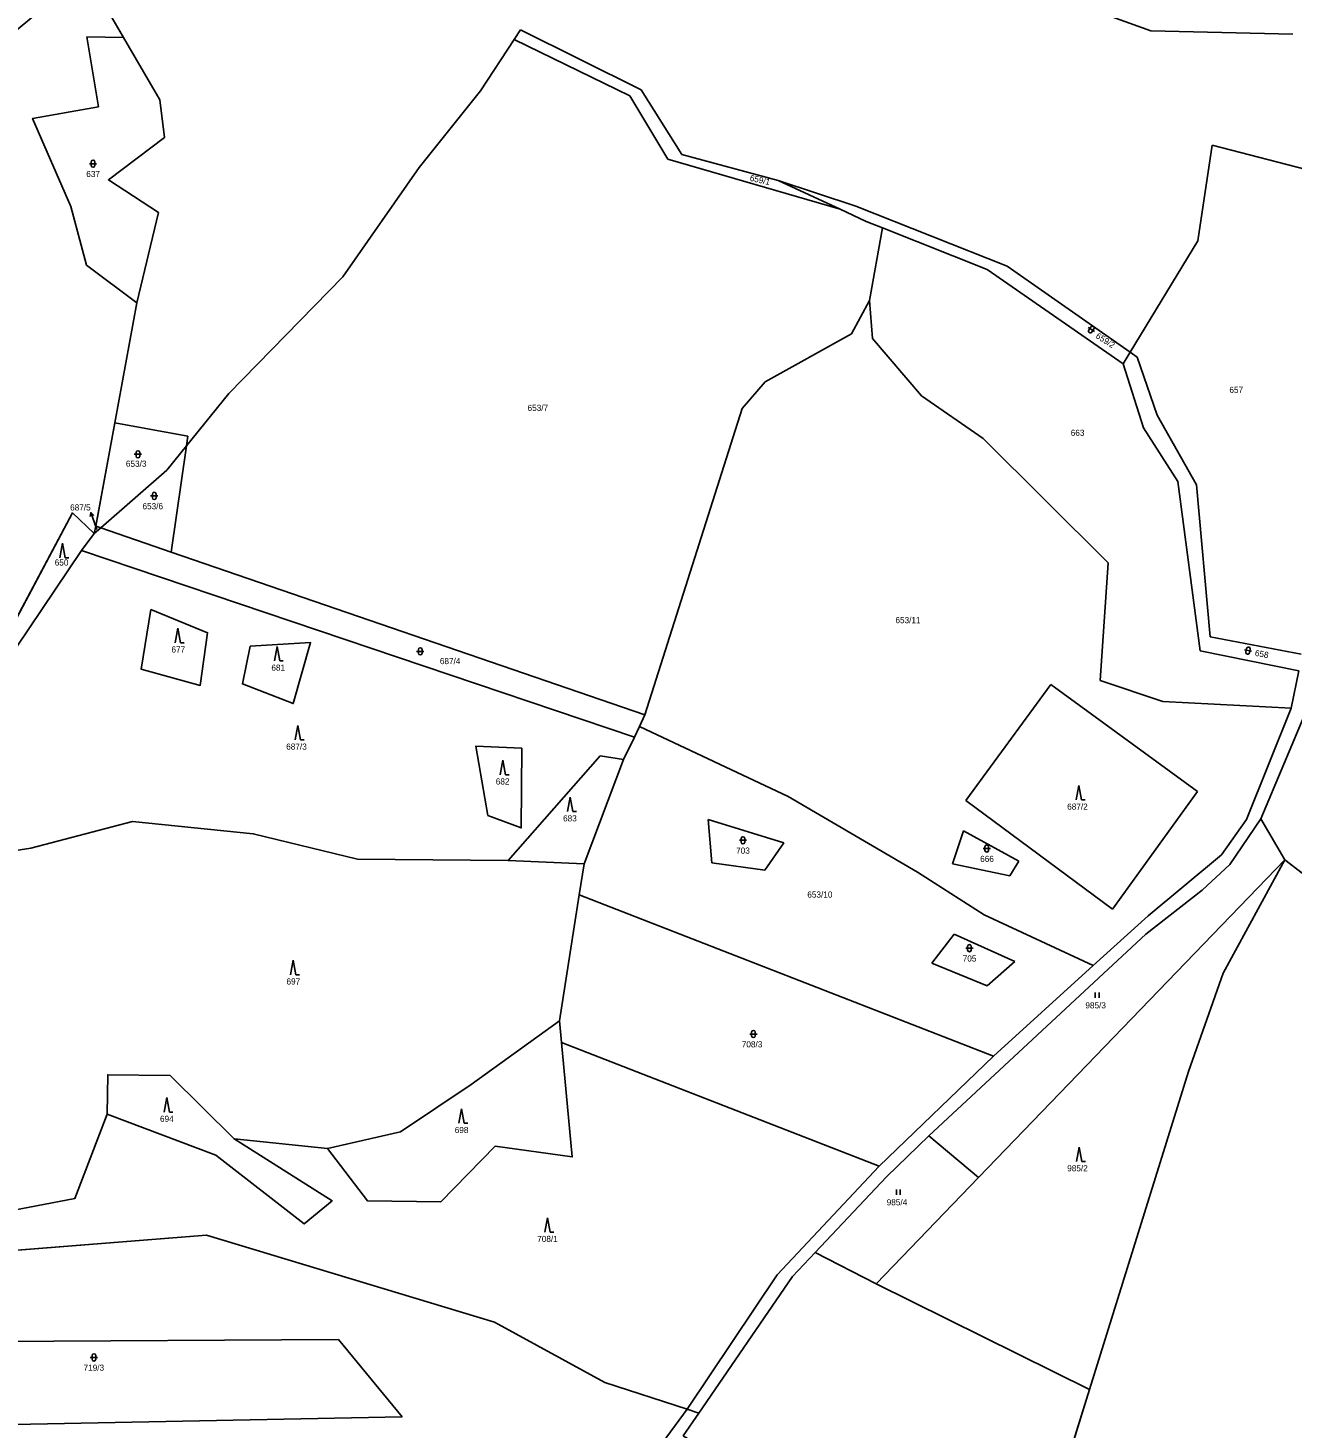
# Model space of a CAD drawing. Extents: x -760642 to -757221, y -1092371 to -1088855.
# Drawn here: x -760077.8 to -759727.7, y -1090939.2 to -1090551.6 of the extents above; entities that cross this region are included whole.
import ezdxf

# ---------------------------------------------------------------- set-up
doc = ezdxf.new("R2010")
doc.units = 0
for name, color, linetype in [('Vrstva 1', 7, 'Continuous'), ('Vrstva 16', 7, 'Continuous'), ('Vrstva 18', 7, 'Continuous'), ('Vrstva 25', 7, 'Continuous'), ('Vrstva 30', 7, 'Continuous')]:
    doc.layers.add(name, color=color, linetype=linetype)

msp = doc.modelspace()

# ---------------------------------------------------------------- linework, layer by layer
at = {"layer": 'Vrstva 1'}
for p, q in [((-759839.3, -1090526.12), (-759766.79, -1090552.4)), ((-760051.34, -1090554.19), (-760060.93, -1090537.68)), ((-759941.44, -1090552.09), (-759943.14, -1090554.79)), ((-759941.44, -1090552.09), (-759907.95, -1090568.71)), ((-759766.79, -1090552.4), (-759727.49, -1090553.28)), ((-760061.5, -1090554.05), (-760051.34, -1090554.19)), ((-760058.3, -1090573.38), (-760061.5, -1090554.05)), ((-760051.34, -1090554.19), (-760041.28, -1090571.5)), ((-759943.14, -1090554.79), (-759952.52, -1090569.01)), ((-759943.14, -1090554.79), (-759911.08, -1090570.33)), ((-760041.28, -1090571.5), (-760040.01, -1090581.94)), ((-759952.52, -1090569.01), (-759969.46, -1090590.23)), ((-759911.08, -1090570.33), (-759900.57, -1090587.91)), ((-759907.95, -1090568.71), (-759896.72, -1090586.57)), ((-760076.56, -1090576.6), (-760058.3, -1090573.38)), ((-760065.98, -1090601.05), (-760076.56, -1090576.6)), ((-760040.01, -1090581.94), (-760055.54, -1090593.66)), ((-759753.81, -1090610.47), (-759749.82, -1090584.03)), ((-759721.29, -1090591.44), (-759749.82, -1090584.03)), ((-759900.57, -1090587.91), (-759852.82, -1090601.75)), ((-759896.72, -1090586.57), (-759870.05, -1090593.84)), ((-759969.46, -1090590.23), (-759990.63, -1090620.44)), ((-760055.54, -1090593.66), (-760041.66, -1090602.71)), ((-759848.53, -1090600.95), (-759870.05, -1090593.84)), ((-759852.82, -1090601.75), (-759870.05, -1090593.84)), ((-760061.65, -1090617.23), (-760065.98, -1090601.05)), ((-760041.66, -1090602.71), (-760047.65, -1090627.66)), ((-759845.63, -1090605.18), (-759852.82, -1090601.75)), ((-759806.57, -1090617.54), (-759848.53, -1090600.95)), ((-759841.14, -1090606.96), (-759845.63, -1090605.18)), ((-759844.72, -1090627.05), (-759841.14, -1090606.96)), ((-759812.16, -1090618.46), (-759841.14, -1090606.96)), ((-759772.52, -1090641.34), (-759753.81, -1090610.47)), ((-760047.65, -1090627.66), (-760061.65, -1090617.23)), ((-759812.16, -1090618.46), (-759774.44, -1090644.53)), ((-759806.57, -1090617.54), (-759772.52, -1090641.34)), ((-759990.63, -1090620.44), (-760022.15, -1090652.82)), ((-760053.78, -1090660.88), (-760047.65, -1090627.66)), ((-759844.72, -1090627.05), (-759849.67, -1090636.31)), ((-759843.88, -1090637.52), (-759844.72, -1090627.05)), ((-759849.67, -1090636.31), (-759873.65, -1090649.58)), ((-759843.88, -1090637.52), (-759830.31, -1090653.45)), ((-759774.44, -1090644.53), (-759772.52, -1090641.34)), ((-759772.52, -1090641.34), (-759770.58, -1090642.7)), ((-759774.44, -1090644.53), (-759768.79, -1090662.29)), ((-759770.58, -1090642.7), (-759765.04, -1090658.8)), ((-759873.65, -1090649.58), (-759879.98, -1090656.97)), ((-760022.15, -1090652.82), (-760033.92, -1090667.25)), ((-759830.31, -1090653.45), (-759813.25, -1090665.24)), ((-759879.98, -1090656.97), (-759906.92, -1090741.78)), ((-760059.06, -1090689.48), (-760053.78, -1090660.88)), ((-760053.78, -1090660.88), (-760033.55, -1090664.64)), ((-759754.19, -1090678.09), (-759765.04, -1090658.8)), ((-760033.55, -1090664.64), (-760033.92, -1090667.25)), ((-759813.25, -1090665.24), (-759778.6, -1090699.65)), ((-759768.79, -1090662.29), (-759759.34, -1090677.14)), ((-760033.92, -1090667.25), (-760039.33, -1090674.03)), ((-760033.92, -1090667.25), (-760038.12, -1090696.68)), ((-760039.33, -1090674.03), (-760057.61, -1090689.98)), ((-759759.34, -1090677.14), (-759753.14, -1090724.03)), ((-759750.34, -1090720.19), (-759754.19, -1090678.09)), ((-760087.49, -1090727.12), (-760065.45, -1090685.86)), ((-760065.45, -1090685.86), (-760059.44, -1090691.57)), ((-760062.97, -1090696.27), (-760059.44, -1090691.57)), ((-760059.44, -1090691.57), (-760059.06, -1090689.48)), ((-760057.61, -1090689.98), (-760059.44, -1090691.57)), ((-760059.06, -1090689.48), (-760057.61, -1090689.98)), ((-760057.61, -1090689.98), (-760038.12, -1090696.68)), ((-760084.8, -1090728.63), (-760062.97, -1090696.27)), ((-760062.97, -1090696.27), (-759909.85, -1090747.94)), ((-760038.12, -1090696.68), (-759906.92, -1090741.78)), ((-759778.6, -1090699.65), (-759780.84, -1090732.24)), ((-760046.45, -1090729.15), (-760043.8, -1090712.57)), ((-760043.8, -1090712.57), (-760028.05, -1090719.03)), ((-760028.05, -1090719.03), (-760030.12, -1090733.62)), ((-760018.44, -1090733.21), (-760016.28, -1090722.76)), ((-760016.28, -1090722.76), (-759999.55, -1090721.77)), ((-759999.55, -1090721.77), (-760004.35, -1090738.67)), ((-759725.13, -1090725), (-759750.34, -1090720.19)), ((-759753.14, -1090724.03), (-759725.83, -1090729.55)), ((-760030.12, -1090733.62), (-760046.45, -1090729.15)), ((-759725.83, -1090729.55), (-759727.9, -1090739.88)), ((-760004.35, -1090738.67), (-760018.44, -1090733.21)), ((-759818.01, -1090765.49), (-759794.48, -1090733.41)), ((-759794.48, -1090733.41), (-759753.88, -1090762.96)), ((-759780.84, -1090732.24), (-759763.48, -1090738.12)), ((-759763.48, -1090738.12), (-759727.9, -1090739.88)), ((-759908.45, -1090744.97), (-759906.92, -1090741.78)), ((-759740.33, -1090770.72), (-759727.9, -1090739.88)), ((-759723.56, -1090740.25), (-759736.34, -1090770.61)), ((-759909.85, -1090747.94), (-759908.45, -1090744.97)), ((-759908.45, -1090744.97), (-759867.29, -1090764.42)), ((-759953.79, -1090750.48), (-759941.06, -1090751.03)), ((-759953.79, -1090750.48), (-759950.43, -1090769.65)), ((-759909.85, -1090747.94), (-759912.88, -1090754.18)), ((-759919.32, -1090753.12), (-759944.83, -1090782.09)), ((-759941.06, -1090751.03), (-759941.21, -1090773.08)), ((-759912.88, -1090754.18), (-759923.74, -1090783.05)), ((-759919.32, -1090753.12), (-759912.88, -1090754.18)), ((-759867.29, -1090764.42), (-759831.42, -1090785.31)), ((-759777.4, -1090795.6), (-759818.01, -1090765.49)), ((-759753.88, -1090762.96), (-759777.4, -1090795.6)), ((-759950.43, -1090769.65), (-759941.21, -1090773.08)), ((-760048.84, -1090771.27), (-760077.05, -1090778.7)), ((-760015.41, -1090774.7), (-760048.84, -1090771.27)), ((-759889.41, -1090770.73), (-759868.42, -1090777.17)), ((-759888.41, -1090782.78), (-759889.41, -1090770.73)), ((-759821.74, -1090783.01), (-759818.71, -1090773.85)), ((-759818.71, -1090773.85), (-759803.33, -1090782.33)), ((-759747.19, -1090780.52), (-759740.33, -1090770.72)), ((-759736.34, -1090770.61), (-759744.91, -1090783.21)), ((-759736.34, -1090770.61), (-759729.65, -1090781.92)), ((-759986.56, -1090781.72), (-760015.41, -1090774.7)), ((-759868.42, -1090777.17), (-759873.72, -1090784.82)), ((-760077.05, -1090778.7), (-760096.06, -1090781.68)), ((-759944.83, -1090782.09), (-759986.56, -1090781.72)), ((-759767.58, -1090797.41), (-759747.19, -1090780.52)), ((-759923.74, -1090783.05), (-759944.83, -1090782.09)), ((-759923.74, -1090783.05), (-759925.15, -1090791.63)), ((-759873.72, -1090784.82), (-759888.41, -1090782.78)), ((-759831.42, -1090785.31), (-759812.95, -1090797.19)), ((-759805.83, -1090786.35), (-759821.74, -1090783.01)), ((-759814.51, -1090869.91), (-759729.65, -1090781.92)), ((-759803.33, -1090782.33), (-759805.83, -1090786.35)), ((-759744.91, -1090783.21), (-759752.54, -1090790.31)), ((-759746.79, -1090813.26), (-759729.65, -1090781.92)), ((-759729.65, -1090781.92), (-759701.91, -1090803.33)), ((-759925.15, -1090791.63), (-759930.58, -1090826.46)), ((-759925.15, -1090791.63), (-759810.36, -1090836.26)), ((-759752.54, -1090790.31), (-759768.22, -1090802.51)), ((-759812.95, -1090797.19), (-759782.77, -1090811.2)), ((-759782.77, -1090811.2), (-759767.58, -1090797.41)), ((-759768.22, -1090802.51), (-759828.32, -1090858.38)), ((-759821.27, -1090802.54), (-759827.48, -1090810.5)), ((-759821.27, -1090802.54), (-759804.44, -1090810.06)), ((-759827.48, -1090810.5), (-759812.1, -1090816.85)), ((-759812.1, -1090816.85), (-759804.44, -1090810.06)), ((-759810.36, -1090836.26), (-759782.77, -1090811.2)), ((-759756.38, -1090840.54), (-759746.79, -1090813.26)), ((-759955.08, -1090844.12), (-759930.58, -1090826.46)), ((-759930.08, -1090832.47), (-759930.58, -1090826.46)), ((-759927.08, -1090864.2), (-759930.08, -1090832.47)), ((-759930.08, -1090832.47), (-759842.06, -1090866.71)), ((-759842.06, -1090866.71), (-759810.36, -1090836.26)), ((-760055.74, -1090841.41), (-760055.93, -1090852.34)), ((-760055.74, -1090841.41), (-760038.4, -1090841.64)), ((-760038.4, -1090841.64), (-760020.72, -1090859.22)), ((-759783.8, -1090928.59), (-759756.38, -1090840.54)), ((-759974.66, -1090857.27), (-759955.08, -1090844.12)), ((-760055.93, -1090852.34), (-760064.86, -1090875.72)), ((-760025.82, -1090863.73), (-760055.93, -1090852.34)), ((-759994.82, -1090861.9), (-760020.72, -1090859.22)), ((-760020.72, -1090859.22), (-759993.57, -1090876.34)), ((-759974.66, -1090857.27), (-759994.82, -1090861.9)), ((-759828.32, -1090858.38), (-759840.03, -1090869.69)), ((-759828.32, -1090858.38), (-759814.51, -1090869.91)), ((-759983.79, -1090876.32), (-759994.82, -1090861.9)), ((-759948.42, -1090861.22), (-759963.44, -1090876.59)), ((-759927.08, -1090864.2), (-759948.42, -1090861.22)), ((-760001.36, -1090882.73), (-760025.82, -1090863.73)), ((-759870.31, -1090896.84), (-759842.06, -1090866.71)), ((-759840.03, -1090869.69), (-759859.79, -1090890.67)), ((-759842.88, -1090899.33), (-759814.51, -1090869.91)), ((-760064.86, -1090875.72), (-760086.21, -1090879.78)), ((-760001.36, -1090882.73), (-759993.57, -1090876.34)), ((-759963.44, -1090876.59), (-759983.79, -1090876.32)), ((-760086.73, -1090890.45), (-760028.38, -1090885.89)), ((-760028.38, -1090885.89), (-759948.63, -1090909.93)), ((-759859.79, -1090890.67), (-759866.07, -1090897.33)), ((-759859.79, -1090890.67), (-759842.88, -1090899.33)), ((-759895.24, -1090934.08), (-759870.31, -1090896.84)), ((-759866.07, -1090897.33), (-759892.01, -1090935.13)), ((-759842.88, -1090899.33), (-759783.8, -1090928.59)), ((-759948.63, -1090909.93), (-759918.06, -1090926.67)), ((-760111.74, -1090915.41), (-759991.78, -1090914.78)), ((-759991.78, -1090914.78), (-759974.21, -1090936.17)), ((-759918.06, -1090926.67), (-759895.24, -1090934.08)), ((-759806.76, -1091002.37), (-759783.8, -1090928.59)), ((-760110.25, -1090938.86), (-759974.21, -1090936.17)), ((-759983.97, -1091053.92), (-759895.24, -1090934.08)), ((-759892.01, -1090935.13), (-759896.31, -1090941.39)), ((-759895.24, -1090934.08), (-759892.01, -1090935.13))]:
    msp.add_line(p, q, dxfattribs=at)
at = {"layer": 'Vrstva 16'}
for p, q in [((-760059.39, -1090688.58), (-760060.431, -1090685.766)), ((-760058.71, -1090690.42), (-760059.39, -1090688.58))]:
    msp.add_line(p, q, dxfattribs=at)
msp.add_lwpolyline([(-760060.553, -1090686.878), (-760060.431, -1090685.766), (-760059.615, -1090686.531)], dxfattribs=at)
at = {"layer": 'Vrstva 25'}
for p, q in [((-760060.8, -1090589.16), (-760058.8, -1090589.16)), ((-760060.3, -1090589.66), (-760060.3, -1090588.66)), ((-760059.3, -1090589.66), (-760059.3, -1090588.66)), ((-759783.981, -1090635.229), (-759783.442, -1090634.387)), ((-759784.133, -1090634.539), (-759782.449, -1090635.617)), ((-759783.139, -1090635.769), (-759782.6, -1090634.926)), ((-760047.86, -1090670.13), (-760047.86, -1090669.13)), ((-760046.86, -1090670.13), (-760046.86, -1090669.13)), ((-760048.36, -1090669.63), (-760046.36, -1090669.63)), ((-760043.35, -1090681.65), (-760043.35, -1090680.65)), ((-760042.35, -1090681.65), (-760042.35, -1090680.65)), ((-760043.85, -1090681.15), (-760041.85, -1090681.15)), ((-760068.272, -1090694.279), (-760069.005, -1090698.279)), ((-760068.272, -1090694.279), (-760067.539, -1090698.279)), ((-760067.539, -1090698.279), (-760066.539, -1090698.279)), ((-760036.292, -1090717.799), (-760037.025, -1090721.799)), ((-760036.292, -1090717.799), (-760035.559, -1090721.799)), ((-760035.559, -1090721.799), (-760034.559, -1090721.799)), ((-760008.822, -1090722.849), (-760009.555, -1090726.849)), ((-760008.822, -1090722.849), (-760008.089, -1090726.849)), ((-759740.442, -1090724.389), (-759740.264, -1090723.405)), ((-759739.459, -1090724.568), (-759739.28, -1090723.584)), ((-760008.089, -1090726.849), (-760007.089, -1090726.849)), ((-759970.17, -1090724.2), (-759968.17, -1090724.2)), ((-759969.67, -1090724.7), (-759969.67, -1090723.7)), ((-759968.67, -1090724.7), (-759968.67, -1090723.7)), ((-759740.845, -1090723.807), (-759738.877, -1090724.165)), ((-760003.062, -1090744.709), (-760003.795, -1090748.709)), ((-760003.062, -1090744.709), (-760002.329, -1090748.709)), ((-760002.329, -1090748.709), (-760001.329, -1090748.709)), ((-759946.292, -1090754.349), (-759947.025, -1090758.349)), ((-759946.292, -1090754.349), (-759945.559, -1090758.349)), ((-759945.559, -1090758.349), (-759944.559, -1090758.349)), ((-759786.752, -1090761.329), (-759787.485, -1090765.329)), ((-759786.752, -1090761.329), (-759786.019, -1090765.329)), ((-759927.642, -1090764.569), (-759928.375, -1090768.569)), ((-759927.642, -1090764.569), (-759926.909, -1090768.569)), ((-759786.019, -1090765.329), (-759785.019, -1090765.329)), ((-759926.909, -1090768.569), (-759925.909, -1090768.569)), ((-759880.78, -1090776.51), (-759878.78, -1090776.51)), ((-759880.28, -1090777.01), (-759880.28, -1090776.01)), ((-759879.28, -1090777.01), (-759879.28, -1090776.01)), ((-759813.25, -1090778.8), (-759811.25, -1090778.8)), ((-759812.75, -1090779.3), (-759812.75, -1090778.3)), ((-759811.75, -1090779.3), (-759811.75, -1090778.3)), ((-759818.05, -1090806.39), (-759816.05, -1090806.39)), ((-759817.55, -1090806.89), (-759817.55, -1090805.89)), ((-759816.55, -1090806.89), (-759816.55, -1090805.89)), ((-760004.382, -1090809.739), (-760005.115, -1090813.739)), ((-760004.382, -1090809.739), (-760003.649, -1090813.739)), ((-760003.649, -1090813.739), (-760002.649, -1090813.739)), ((-759782.177, -1090818.625), (-759782.177, -1090820.125)), ((-759781.155, -1090820.125), (-759781.155, -1090818.625)), ((-759877.88, -1090830.15), (-759875.88, -1090830.15)), ((-759877.38, -1090830.65), (-759877.38, -1090829.65)), ((-759876.38, -1090830.65), (-759876.38, -1090829.65)), ((-760039.392, -1090847.769), (-760040.125, -1090851.769)), ((-760039.392, -1090847.769), (-760038.659, -1090851.769)), ((-759957.722, -1090850.869), (-759958.455, -1090854.869)), ((-759957.722, -1090850.869), (-759956.989, -1090854.869)), ((-760038.659, -1090851.769), (-760037.659, -1090851.769)), ((-759956.989, -1090854.869), (-759955.989, -1090854.869)), ((-759786.662, -1090861.469), (-759787.395, -1090865.469)), ((-759786.662, -1090861.469), (-759785.929, -1090865.469)), ((-759785.929, -1090865.469), (-759784.929, -1090865.469)), ((-759837.287, -1090873.165), (-759837.287, -1090874.665)), ((-759836.265, -1090874.665), (-759836.265, -1090873.165)), ((-759933.892, -1090881.029), (-759934.625, -1090885.029)), ((-759933.892, -1090881.029), (-759933.159, -1090885.029)), ((-759933.159, -1090885.029), (-759932.159, -1090885.029)), ((-760060.56, -1090919.7), (-760058.56, -1090919.7)), ((-760060.06, -1090920.2), (-760060.06, -1090919.2)), ((-760059.06, -1090920.2), (-760059.06, -1090919.2))]:
    msp.add_line(p, q, dxfattribs=at)
for centre, start, end in [((-760059.8, -1090588.66), 0, 180), ((-760059.8, -1090589.66), 180, 0), ((-759783.021, -1090634.657), 327.37086, 147.37086), ((-759783.56, -1090635.499), 147.37086, 327.37086), ((-760047.36, -1090669.13), 0, 180), ((-760047.36, -1090670.13), 180, 0), ((-760042.85, -1090680.65), 0, 180), ((-760042.85, -1090681.65), 180, 0), ((-759969.17, -1090723.7), 0, 180), ((-759739.772, -1090723.494), 349.69527, 169.69527), ((-759969.17, -1090724.7), 180, 0), ((-759739.951, -1090724.478), 169.69527, 349.69527), ((-759879.78, -1090776.01), 0, 180), ((-759879.78, -1090777.01), 180, 0), ((-759812.25, -1090778.3), 0, 180), ((-759812.25, -1090779.3), 180, 0), ((-759817.05, -1090805.89), 0, 180), ((-759817.05, -1090806.89), 180, 0), ((-759876.88, -1090829.65), 0, 180), ((-759876.88, -1090830.65), 180, 0), ((-760059.56, -1090919.2), 0, 180), ((-760059.56, -1090920.2), 180, 0)]:
    msp.add_arc(centre, 0.5, start, end, dxfattribs=at)
at = {"layer": 'Vrstva 30'}
for points in [[(-760087.49, -1090727.12), (-760065.45, -1090685.86), (-760059.44, -1090691.57), (-760059.06, -1090689.48), (-760059.059, -1090689.475), (-760053.78, -1090660.88), (-760047.65, -1090627.66), (-760061.65, -1090617.23), (-760065.98, -1090601.05), (-760076.56, -1090576.6), (-760058.3, -1090573.38), (-760061.5, -1090554.05), (-760051.34, -1090554.19), (-760060.93, -1090537.68), (-760063.87, -1090540.48), (-760069.73, -1090544.04), (-760075.22, -1090547.37), (-760092.34, -1090561.46)], [(-760051.34, -1090554.19), (-760061.5, -1090554.05), (-760058.3, -1090573.38), (-760076.56, -1090576.6), (-760065.98, -1090601.05), (-760061.65, -1090617.23), (-760047.65, -1090627.66), (-760041.66, -1090602.71), (-760055.54, -1090593.66), (-760040.01, -1090581.94), (-760041.28, -1090571.5), (-760051.34, -1090554.19)], [(-760087.49, -1090727.12), (-760084.8, -1090728.63), (-760062.97, -1090696.27), (-760059.44, -1090691.57), (-760065.45, -1090685.86), (-760087.49, -1090727.12)], [(-760099.33, -1090756.13), (-760096.06, -1090781.68), (-760077.05, -1090778.7), (-760048.84, -1090771.27), (-760015.41, -1090774.7), (-759986.56, -1090781.72), (-759944.83, -1090782.09), (-759919.32, -1090753.12), (-759912.88, -1090754.18), (-759909.85, -1090747.94), (-760062.97, -1090696.27), (-760084.8, -1090728.63), (-760101.49, -1090737.46), (-760113.71, -1090753.05), (-760099.33, -1090756.13)], [(-760043.8, -1090712.57), (-760046.45, -1090729.15), (-760030.12, -1090733.62), (-760028.05, -1090719.03), (-760043.8, -1090712.57)], [(-760016.28, -1090722.76), (-760018.44, -1090733.21), (-760004.35, -1090738.67), (-759999.55, -1090721.77), (-760016.28, -1090722.76)], [(-759950.43, -1090769.65), (-759941.21, -1090773.08), (-759941.06, -1090751.03), (-759953.79, -1090750.48), (-759950.43, -1090769.65)], [(-759919.32, -1090753.12), (-759944.83, -1090782.09), (-759923.74, -1090783.05), (-759912.88, -1090754.18), (-759919.32, -1090753.12)], [(-759994.82, -1090861.9), (-759974.66, -1090857.27), (-759955.08, -1090844.12), (-759930.58, -1090826.46), (-759925.15, -1090791.63), (-759923.74, -1090783.05), (-759944.83, -1090782.09), (-759986.56, -1090781.72), (-760015.41, -1090774.7), (-760048.84, -1090771.27), (-760077.05, -1090778.7), (-760096.06, -1090781.68), (-760084.09, -1090840.66), (-760086.21, -1090879.78), (-760064.86, -1090875.72), (-760055.93, -1090852.34), (-760055.74, -1090841.41), (-760038.4, -1090841.64), (-760020.72, -1090859.22), (-759994.82, -1090861.9)], [(-759842.88, -1090899.33), (-759783.8, -1090928.59), (-759756.38, -1090840.54), (-759746.79, -1090813.26), (-759729.65, -1090781.92), (-759814.51, -1090869.91), (-759842.88, -1090899.33)], [(-759701.91, -1090803.33), (-759729.65, -1090781.92), (-759746.79, -1090813.26)], [(-759746.79, -1090813.26), (-759756.38, -1090840.54), (-759783.8, -1090928.59), (-759806.76, -1091002.37), (-759778.18, -1091009.55), (-759753.33, -1091001.99), (-759736.18, -1091004.6), (-759707.65, -1091014.61)], [(-759930.08, -1090832.47), (-759930.58, -1090826.46), (-759955.08, -1090844.12), (-759974.66, -1090857.27), (-759994.82, -1090861.9), (-759983.79, -1090876.32), (-759963.44, -1090876.59), (-759948.42, -1090861.22), (-759927.08, -1090864.2), (-759930.08, -1090832.47)], [(-759994.82, -1090861.9), (-760020.72, -1090859.22), (-759993.57, -1090876.34), (-760001.36, -1090882.73), (-760025.82, -1090863.73), (-760055.93, -1090852.34), (-760064.86, -1090875.72), (-760086.21, -1090879.78), (-760086.73, -1090890.45), (-760028.38, -1090885.89), (-759948.63, -1090909.93), (-759918.06, -1090926.67), (-759895.24, -1090934.08), (-759870.31, -1090896.84), (-759842.06, -1090866.71), (-759930.08, -1090832.47), (-759927.08, -1090864.2), (-759948.42, -1090861.22), (-759963.44, -1090876.59), (-759983.79, -1090876.32), (-759994.82, -1090861.9)], [(-760055.74, -1090841.41), (-760055.93, -1090852.34), (-760025.82, -1090863.73), (-760001.36, -1090882.73), (-759993.57, -1090876.34), (-760020.72, -1090859.22), (-760038.4, -1090841.64), (-760055.74, -1090841.41)], [(-759877.14, -1090953.63), (-759867.4, -1090961.14), (-759865.02, -1090987.83), (-759828.7, -1091004.09), (-759808.17, -1091011.49), (-759806.76, -1091002.37), (-759783.8, -1090928.59), (-759842.88, -1090899.33), (-759859.79, -1090890.67), (-759866.07, -1090897.33), (-759892.01, -1090935.13), (-759896.31, -1090941.39), (-759877.85, -1090953.08), (-759877.14, -1090953.63)]]:
    msp.add_lwpolyline(points, dxfattribs=at)

# ---------------------------------------------------------------- texts
at = {"layer": 'Vrstva 16'}
msp.add_text('687/5', height=1.7, dxfattribs=at).set_placement((-760066.147, -1090685.18))
at = {"layer": 'Vrstva 18'}
for s, height, p in [('637', 1.7, (-760061.67, -1090592.86)), ('657', 1.7, (-759745.04, -1090652.64)), ('653/7', 1.7, (-759939.44, -1090657.62)), ('663', 1.7, (-759788.98, -1090664.52)), ('653/3', 1.7, (-760050.69, -1090673.08)), ('653/6', 1.7, (-760046.1, -1090684.85)), ('687/5', 0.1, (-760058.852, -1090690.42)), ('650', 1.7, (-760070.41, -1090700.43)), ('653/11', 1.7, (-759837.54, -1090716.39)), ('677', 1.7, (-760038.08, -1090724.51)), ('687/4', 1.7, (-759963.73, -1090727.73)), ('681', 1.7, (-760010.4, -1090729.56)), ('687/3', 1.7, (-760006.29, -1090751.42)), ('682', 1.7, (-759948.24, -1090761.06)), ('687/2', 1.7, (-759789.97, -1090768.04)), ('683', 1.7, (-759929.604, -1090771.28)), ('703', 1.7, (-759881.67, -1090780.21)), ('666', 1.7, (-759814.07, -1090782.5)), ('653/10', 1.7, (-759861.95, -1090792.38)), ('705', 1.7, (-759818.9, -1090810.09)), ('697', 1.7, (-760006.21, -1090816.45)), ('985/3', 1.7, (-759784.93, -1090823.06)), ('708/3', 1.7, (-759880.098, -1090833.85)), ('694', 1.7, (-760041.25, -1090854.48)), ('698', 1.7, (-759959.61, -1090857.58)), ('985/2', 1.7, (-759789.959, -1090868.18)), ('985/4', 1.7, (-759839.96, -1090877.6)), ('708/1', 1.7, (-759936.764, -1090887.74)), ('719/3', 1.7, (-760062.42, -1090923.4))]:
    msp.add_text(s, height=height, dxfattribs=at).set_placement(p)
for s, rotation, p in [('659/1', 346.95441, (-759878.01, -1090593.84)), ('659/2', 327.37086, (-759782.23, -1090637.27)), ('658', 349.69518, (-759738.08, -1090725.42))]:
    msp.add_text(s, height=1.7, rotation=rotation, dxfattribs=at).set_placement(p)

doc.saveas('drawing.dxf')
